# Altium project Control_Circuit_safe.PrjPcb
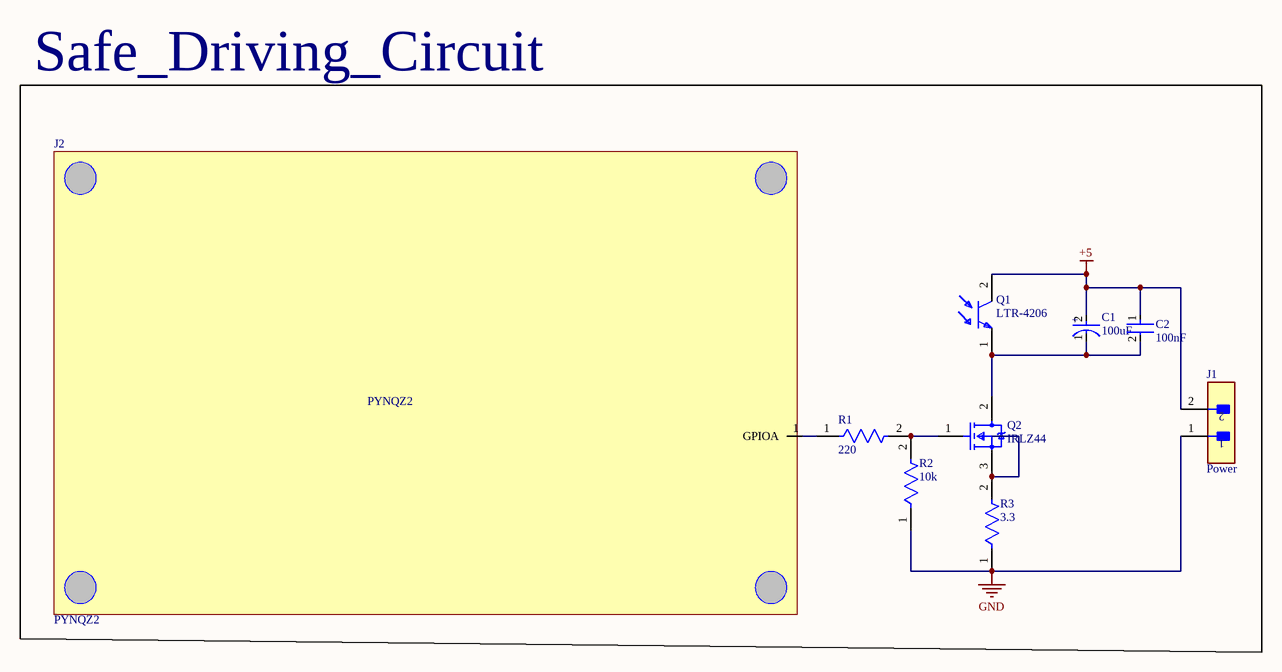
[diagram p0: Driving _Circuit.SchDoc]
1 sheet, 9 parts. Net scope: global (net labels, ports and power ports of the same name join across sheets).
Board file: Control_Circuit_PCB.PcbDoc

## Sheet Driving _Circuit.SchDoc
size A4; SheetNumber: 1; SheetTotal: 1; SPICEModelCacheBUJQYFZZ: <root> / <DocumentId>BUJQYFZZ</DocumentId> / </root>

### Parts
C1  100uF  [FP-RAD-TH-D_6_3_0_5-L_11-MFG]
C2  100nF  [FP-GCE21B-0_3-MFG]
J1  Power  [FP-TMM-102-03-T-S-MFG]
J2  PYNQZ2  [PYNQZ2_board]
Q1  LTR-4206  [FP-LTR-4206-MFG]
Q2  IRLZ44  [FP-PG-TO220-3-MFG]
R1  220  [FP-MCU0805-IPC_B]
R2  10k  [FP-CRGCQ1210-IPC_C]
R3  3.3  [FP-RMCF0805-IPC_A]

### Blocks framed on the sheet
Safe_Driving_Circuit: C1 C2 J1 J2 Q1 Q2 R1-R3

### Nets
+5: C1.2(A) C2.1 J1.2 Q1.2(C)
GND: J1.1 R2.1 R3.1
NetC1_1: C1.1(C) C2.2 Q1.1(E) Q2.2(D)
NetJ2_1: J2.1(GPIOA) R1.1
NetQ2_1: Q2.1(G) R1.2 R2.2
NetQ2_3: Q2.3(S) R3.2

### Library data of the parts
C1 = CMP-05427-000856-1: Aluminum Electrolytic Capacitors (Radial Lead Type) 100uF ±20% 25V; Lead Diameter: 0.5mm; Polarity: Polar; Ripple Current: 455mA; Impedance: 130mR; Life (Hours): 2000Hour
C2 = CMP-06035-010744-1: Ceramic Capacitor 100nF ±20% 100V X7R 0805
J1 = CMP-02766-001621-1: CONN HEADER VERT 2POS 2MM; Max Voltage Rating (AC): 500V; Gender: Male; Number of Positions: 2; Max Current Rating: 3.9A
Q1 = CMP-22030-000001-1: SENSOR PHOTO 940NM TOP VIEW T1; Manufacturer: Lite-On; Viewing Angle: 20°; Wavelength: 900nm; Fall Time: 10us; Dark Current: 0.1uA; Collector Emitter Breakdown Voltage: 30V; Power Dissipation: 100mW; Max Collector Current: 9.6mA
Q2 = CMP-32901-000488-1: MOSFET N-CH 55V 47A TO220AB; Turn-On Delay Time: 11ns; Gate to Source Voltage (Vgs): 16V; Element Configuration: Single; Rds On Max: 22mR; Turn-Off Delay Time: 26ns; Max Power Dissipation: 110W; Threshold Voltage: 2V; Drain to Source Resistance: 35mR; Input Capacitance: 1.7nF
R1 = CMP-02407-000312-1: RES 1.05K OHM 0.5% 1/5W 0805; Resistance: 220R; Tolerance: 0.1%; Temperature Coefficient: 25ppm/°C; Max Power Dissipation: 125mW
R2 = CMP-03211-005276-1: CRGCQ1210 10KΩ 0.5W ±100ppm/°C 1% 200V; Manufacturer Part Number: CRGCQ1210F10K; Manufacturer: TE Connectivity; Automotive Grade: Grade 913; Tolerance: 0.01
R3 = CMP-26527-003650-1: 3.3Ω ±5% 0.125W 0805 Thick Film Chip Resistor AEC-Q200 compliant; Max Power Dissipation: 125mW; Resistance: 3.3R; Temperature Coefficient: 200ppm/°C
